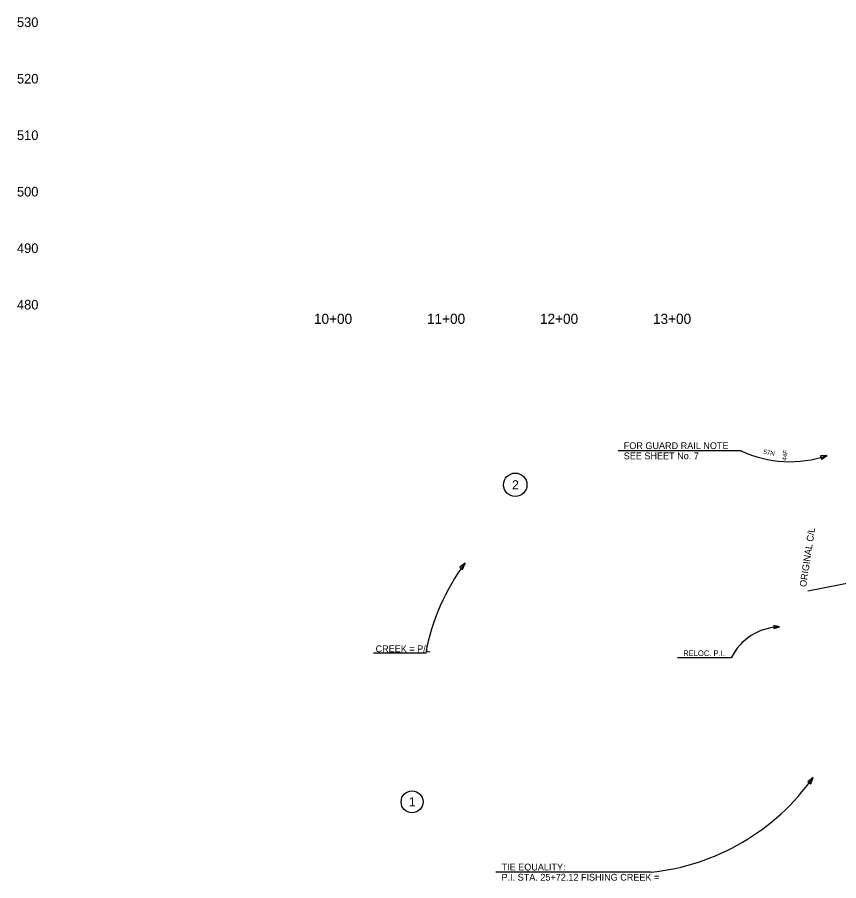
# Model space of a CAD drawing. Extents: x 1964849 to 1967422, y 1116563 to 1122210.
# Drawn here: x 1965766 to 1966493, y 1120670 to 1121434 of the extents above; entities that cross this region are included whole.
import ezdxf

# ---------------------------------------------------------------- set-up
doc = ezdxf.new("R2010")
doc.units = 0
for name, color, linetype in [('RD_DDB_Profile_Elev', 7, 'Continuous'), ('RD_DDB_StaTX', 7, 'Continuous'), ('RD_EX_DV_Prop', 7, 'Continuous'), ('RD_EX_DV_TX_Prop', 7, 'Continuous'), ('RD_HC_Data', 7, 'Continuous'), ('RD_HC_Data_Rel', 7, 'Continuous'), ('RD_PD_TX_CstnLmt', 7, 'Continuous'), ('RD_TX_Drainage', 7, 'Continuous'), ('RD_TX_Misc1', 7, 'Continuous'), ('RD_TX_RoadID', 7, 'Continuous')]:
    doc.layers.add(name, color=color, linetype=linetype)

msp = doc.modelspace()

# ---------------------------------------------------------------- linework, layer by layer
at = {"layer": 'RD_EX_DV_Prop'}
msp.add_line((1966465.82, 1120926.48), (1966952.36, 1121022.03), dxfattribs=at)
at = {"layer": 'RD_EX_DV_TX_Prop'}
msp.add_line((1966127.58, 1120871.27), (1966081.28, 1120871.27), dxfattribs=at)
msp.add_lwpolyline([(1966160.28, 1120945.54), (1966162.51, 1120951.11), (1966157.79, 1120947.4)], close=True, dxfattribs=at)
for centre, radius in [((1966206.86, 1121020.43), 10.35), ((1966115.57, 1120739.82), 9.72)]:
    msp.add_circle(centre, radius, dxfattribs=at)
msp.add_arc((1966314.94, 1120836.87), 190.49, 143.14971, 169.5955, dxfattribs=at)
at = {"layer": 'RD_HC_Data'}
msp.add_line((1966327.04, 1120677.59), (1966189.74, 1120677.59), dxfattribs=at)
msp.add_lwpolyline([(1966468.39, 1120755.82), (1966470.47, 1120761.45), (1966465.85, 1120757.61)], close=True, dxfattribs=at)
msp.add_arc((1966306.42, 1120877.46), 200.93, 275.89189, 324.73454, dxfattribs=at)
at = {"layer": 'RD_HC_Data_Rel'}
msp.add_line((1966398, 1120867.33), (1966350.55, 1120867.33), dxfattribs=at)
msp.add_lwpolyline([(1966435.75, 1120893.21), (1966440.54, 1120894.64), (1966435.68, 1120895.79)], close=True, dxfattribs=at)
msp.add_arc((1966441.92, 1120845.69), 48.97, 91.61475, 153.7786, dxfattribs=at)
at = {"layer": 'RD_TX_Misc1'}
msp.add_line((1966406.78, 1121050.52), (1966297.85, 1121050.52), dxfattribs=at)
msp.add_lwpolyline([(1966477.87, 1121043.06), (1966482.82, 1121046.44), (1966476.84, 1121045.98)], close=True, dxfattribs=at)
msp.add_arc((1966449.73, 1121140.43), 99.63, 244.46334, 289.39296, dxfattribs=at)

# ---------------------------------------------------------------- texts
at = {"layer": 'RD_DDB_Profile_Elev'}
for s, p in [('530', (1965765.92, 1121425.58)), ('520', (1965765.92, 1121375.58)), ('510', (1965765.92, 1121325.58)), ('500', (1965765.92, 1121275.58)), ('490', (1965765.92, 1121225.58)), ('480', (1965765.92, 1121175.58))]:
    msp.add_text(s, height=8.5, dxfattribs=at).set_placement(p)
at = {"layer": 'RD_DDB_StaTX'}
for s, p in [('10+00', (1966028.71, 1121162.83)), ('11+00', (1966128.71, 1121162.83)), ('12+00', (1966228.71, 1121162.83)), ('13+00', (1966328.71, 1121162.83))]:
    msp.add_text(s, height=9, dxfattribs=at).set_placement(p)
at = {"layer": 'RD_EX_DV_TX_Prop'}
for s, height, p in [('2', 8, (1966204.02, 1121016.44)), ('CREEK = P/L', 6, (1966083.28, 1120872.27)), ('1', 8, (1966112.65, 1120735.83))]:
    msp.add_text(s, height=height, dxfattribs=at).set_placement(p)
at = {"layer": 'RD_HC_Data'}
for s, p in [('TIE EQUALITY:', (1966194.74, 1120679.09)), ('P.I. STA. 25+72.12 FISHING CREEK =', (1966194.74, 1120670.09))]:
    msp.add_text(s, height=6, dxfattribs=at).set_placement(p)
at = {"layer": 'RD_HC_Data_Rel'}
msp.add_text('RELOC. P.I.', height=5, dxfattribs=at).set_placement((1966355.55, 1120868.83))
at = {"layer": 'RD_PD_TX_CstnLmt'}
msp.add_text('44F', height=4, rotation=79.36544, dxfattribs=at).set_placement((1966446.64, 1121041.48))
at = {"layer": 'RD_TX_Drainage'}
msp.add_text('57N', height=4, rotation=349.42904, dxfattribs=at).set_placement((1966426.15, 1121047.87))
at = {"layer": 'RD_TX_Misc1'}
for s, p in [('FOR GUARD RAIL NOTE', (1966302.85, 1121052.02)), ('SEE SHEET No. 7', (1966302.85, 1121043.02))]:
    msp.add_text(s, height=6, dxfattribs=at).set_placement(p)
at = {"layer": 'RD_TX_RoadID'}
msp.add_text('ORIGINAL C/L', height=6, rotation=81.38837, dxfattribs=at).set_placement((1966464.28, 1120929.64))

doc.saveas('drawing.dxf')
